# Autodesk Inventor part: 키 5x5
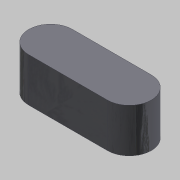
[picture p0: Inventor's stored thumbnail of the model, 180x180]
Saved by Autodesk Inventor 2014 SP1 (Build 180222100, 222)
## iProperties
Created: 2016-04
Part Number: 키 5x5
Document SubType Name: Modeling
Designer: mdu
Density: 7.86 g/cm^3
Mass: 2.54015 g
Surface Area: 2.9781 cm^2
Volume: 0.323175 cm^3
Material: 강철, 연강
Appearance: 강철 - 광택
Author: mdu
Revision Number: 1
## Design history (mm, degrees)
sketch "스케치1"
  geometry: L1 (-4.5, -2.5)-(4.5, -2.5); L2 (4.5, 2.5)-(-4.5, 2.5); A1 r 2.5 centre (4.5, 0) between (4.5, -2.5) and (4.5, 2.5); A2 r 2.5 centre (-4.5, 0) between (-4.5, 2.5) and (-4.5, -2.5); 2 further points
  constraints: 4 end point, 4 point on circle, 4 tangent, 2 centre point, 1 horizontal, 1 horizontal alignment, 1 midpoint, 1 parallel, 1 vertical alignment
  dimensions: "d0" = 5 distance between parallel lines of L1 L2; "d1" = 14 dimension on A1 A2
extrude "돌출1" new body sketch "스케치1" stored distance "d2" = 5; taper "d3" = 0 deg
node "솔리드1"
